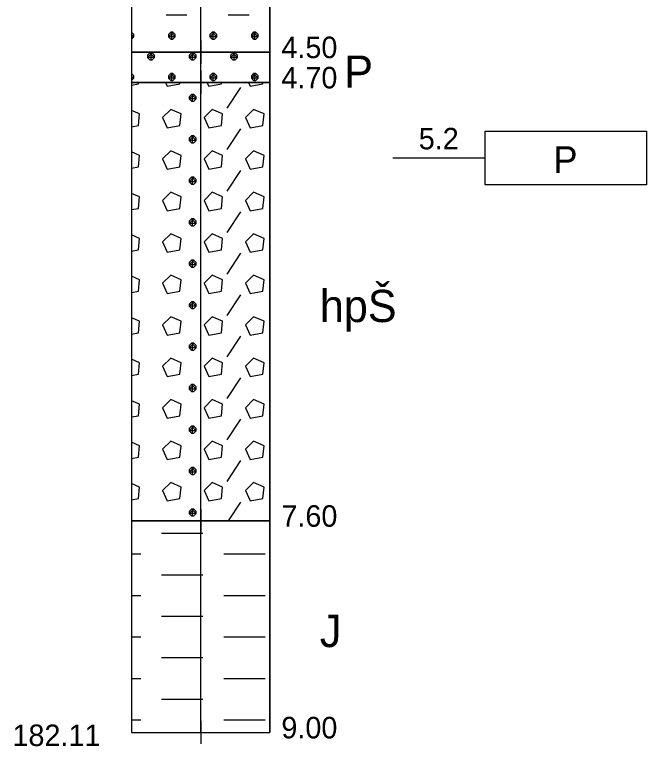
# Model space of a CAD drawing. Extents: x 3042 to 4120, y 576 to 2694.
# Drawn here: x 3706.2 to 3727.08, y 1007.43 to 1031.63 of the extents above; entities that cross this region are included whole.
import ezdxf

# ---------------------------------------------------------------- set-up
doc = ezdxf.new("R2010")
doc.units = 0
for name, color, linetype in [('17', 7, 'Continuous'), ('18', 7, 'Continuous'), ('51', 7, 'Continuous'), ('52', 7, 'Continuous'), ('53', 7, 'Continuous'), ('56', 7, 'Continuous'), ('62', 7, 'Continuous')]:
    doc.layers.add(name, color=color, linetype=linetype)

msp = doc.modelspace()

# ---------------------------------------------------------------- linework, layer by layer
at = {"layer": '18'}
for p, q in [((3712.347, 1007.89), (3712.347, 1052.89)), ((3712.347, 1008.271), (3712.347, 1007.509)), ((3711.966, 1007.89), (3712.728, 1007.89))]:
    msp.add_line(p, q, dxfattribs=at)
at = {"layer": '51'}
for p, q in [((3711.201, 1031.623), (3711.887, 1031.623)), ((3713.259, 1031.623), (3713.944, 1031.623)), ((3710.058, 1031.051), (3710.058, 1031.051)), ((3711.392, 1030.822), (3711.392, 1031.051)), ((3712.763, 1030.822), (3712.763, 1031.051)), ((3714.135, 1030.822), (3714.135, 1031.051)), ((3710.706, 1030.137), (3710.706, 1030.365)), ((3712.077, 1030.137), (3712.077, 1030.365)), ((3713.449, 1030.137), (3713.449, 1030.365)), ((3710.058, 1029.679), (3710.058, 1029.679)), ((3711.392, 1029.451), (3711.392, 1029.679)), ((3712.763, 1029.451), (3712.763, 1029.679)), ((3714.135, 1029.451), (3714.135, 1029.679)), ((3713.22, 1028.536), (3713.678, 1029.222)), ((3712.077, 1028.765), (3712.077, 1028.994)), ((3713.22, 1027.165), (3713.678, 1027.851)), ((3712.077, 1027.393), (3712.077, 1027.622)), ((3713.22, 1025.793), (3713.678, 1026.479)), ((3712.077, 1026.022), (3712.077, 1026.25)), ((3713.22, 1024.422), (3713.678, 1025.107)), ((3712.077, 1024.65), (3712.077, 1024.879)), ((3713.22, 1023.05), (3713.678, 1023.736)), ((3712.077, 1023.279), (3712.077, 1023.507)), ((3713.22, 1021.678), (3713.678, 1022.364)), ((3712.077, 1021.907), (3712.077, 1022.136)), ((3713.22, 1020.307), (3713.678, 1020.993)), ((3712.077, 1020.535), (3712.077, 1020.764)), ((3713.22, 1018.935), (3713.678, 1019.621)), ((3712.077, 1019.164), (3712.077, 1019.392)), ((3713.22, 1017.564), (3713.678, 1018.249)), ((3712.077, 1017.792), (3712.077, 1018.021)), ((3713.22, 1016.192), (3713.678, 1016.878)), ((3712.077, 1016.421), (3712.077, 1016.649)), ((3713.267, 1014.89), (3713.678, 1015.506)), ((3712.077, 1015.049), (3712.077, 1015.278)), ((3711.049, 1014.478), (3711.735, 1014.478)), ((3711.735, 1014.478), (3712.42, 1014.478)), ((3710.061, 1013.792), (3710.363, 1013.792)), ((3713.106, 1013.792), (3713.792, 1013.792)), ((3713.792, 1013.792), (3714.478, 1013.792)), ((3711.049, 1013.106), (3711.735, 1013.106)), ((3711.735, 1013.106), (3712.42, 1013.106)), ((3710.061, 1012.42), (3710.363, 1012.42)), ((3713.106, 1012.42), (3713.792, 1012.42)), ((3713.792, 1012.42), (3714.478, 1012.42)), ((3711.049, 1011.734), (3711.735, 1011.734)), ((3711.735, 1011.734), (3712.42, 1011.734)), ((3710.061, 1011.049), (3710.363, 1011.049)), ((3713.106, 1011.049), (3713.792, 1011.049)), ((3713.792, 1011.049), (3714.478, 1011.049)), ((3711.049, 1010.363), (3711.735, 1010.363)), ((3711.735, 1010.363), (3712.42, 1010.363)), ((3710.061, 1009.677), (3710.363, 1009.677)), ((3713.106, 1009.677), (3713.792, 1009.677)), ((3713.792, 1009.677), (3714.478, 1009.677)), ((3711.049, 1008.991), (3711.735, 1008.991)), ((3711.735, 1008.991), (3712.42, 1008.991)), ((3710.061, 1008.305), (3710.363, 1008.305)), ((3713.106, 1008.305), (3713.792, 1008.305)), ((3713.792, 1008.305), (3714.478, 1008.305))]:
    msp.add_line(p, q, dxfattribs=at)
for points in [[(3710.061, 1030.39), (3714.633, 1030.39), (3714.633, 1034.89), (3710.061, 1034.89)], [(3710.061, 1029.39), (3714.633, 1029.39), (3714.633, 1030.39), (3710.061, 1030.39)], [(3710.061, 1014.89), (3714.633, 1014.89), (3714.633, 1029.39), (3710.061, 1029.39)], [(3710.061, 1007.89), (3714.633, 1007.89), (3714.633, 1014.89), (3710.061, 1014.89)]]:
    msp.add_lwpolyline(points, close=True, dxfattribs=at)
for points in [[(3710.058, 1030.822), (3710.058, 1030.822), (3710.134, 1030.899), (3710.134, 1030.975), (3710.058, 1031.051), (3710.058, 1031.051)], [(3710.061, 1030.972), (3710.134, 1030.899), (3710.061, 1030.899)], [(3711.354, 1031.051), (3711.277, 1030.975), (3711.277, 1030.899), (3711.354, 1030.822), (3711.43, 1030.822), (3711.506, 1030.899), (3711.506, 1030.975), (3711.43, 1031.051), (3711.354, 1031.051), (3711.506, 1030.899), (3711.277, 1030.899), (3711.43, 1031.051)], [(3712.725, 1031.051), (3712.649, 1030.975), (3712.649, 1030.899), (3712.725, 1030.822), (3712.801, 1030.822), (3712.878, 1030.899), (3712.878, 1030.975), (3712.801, 1031.051), (3712.725, 1031.051), (3712.878, 1030.899), (3712.649, 1030.899), (3712.801, 1031.051)], [(3714.097, 1031.051), (3714.021, 1030.975), (3714.021, 1030.899), (3714.097, 1030.822), (3714.173, 1030.822), (3714.249, 1030.899), (3714.249, 1030.975), (3714.173, 1031.051), (3714.097, 1031.051), (3714.249, 1030.899), (3714.021, 1030.899), (3714.173, 1031.051)], [(3710.668, 1030.365), (3710.592, 1030.289), (3710.592, 1030.213), (3710.668, 1030.137), (3710.744, 1030.137), (3710.82, 1030.213), (3710.82, 1030.289), (3710.744, 1030.365), (3710.668, 1030.365), (3710.82, 1030.213), (3710.592, 1030.213), (3710.744, 1030.365)], [(3712.039, 1030.365), (3711.963, 1030.289), (3711.963, 1030.213), (3712.039, 1030.137), (3712.116, 1030.137), (3712.192, 1030.213), (3712.192, 1030.289), (3712.116, 1030.365), (3712.039, 1030.365), (3712.192, 1030.213), (3711.963, 1030.213), (3712.116, 1030.365)], [(3713.411, 1030.365), (3713.335, 1030.289), (3713.335, 1030.213), (3713.411, 1030.137), (3713.487, 1030.137), (3713.563, 1030.213), (3713.563, 1030.289), (3713.487, 1030.365), (3713.411, 1030.365), (3713.563, 1030.213), (3713.335, 1030.213), (3713.487, 1030.365)], [(3710.058, 1029.451), (3710.058, 1029.451), (3710.134, 1029.527), (3710.134, 1029.603), (3710.058, 1029.679), (3710.058, 1029.679)], [(3711.354, 1029.679), (3711.277, 1029.603), (3711.277, 1029.527), (3711.354, 1029.451), (3711.43, 1029.451), (3711.506, 1029.527), (3711.506, 1029.603), (3711.43, 1029.679), (3711.354, 1029.679), (3711.506, 1029.527), (3711.277, 1029.527), (3711.43, 1029.679)], [(3712.725, 1029.679), (3712.649, 1029.603), (3712.649, 1029.527), (3712.725, 1029.451), (3712.801, 1029.451), (3712.878, 1029.527), (3712.878, 1029.603), (3712.801, 1029.679), (3712.725, 1029.679), (3712.878, 1029.527), (3712.649, 1029.527), (3712.801, 1029.679)], [(3714.097, 1029.679), (3714.021, 1029.603), (3714.021, 1029.527), (3714.097, 1029.451), (3714.173, 1029.451), (3714.249, 1029.527), (3714.249, 1029.603), (3714.173, 1029.679), (3714.097, 1029.679), (3714.249, 1029.527), (3714.021, 1029.527), (3714.173, 1029.679)], [(3710.061, 1029.601), (3710.134, 1029.527), (3710.061, 1029.527)], [(3710.061, 1029.295), (3710.287, 1029.337), (3710.292, 1029.39)], [(3711.182, 1029.39), (3711.239, 1029.26), (3711.658, 1029.337), (3711.664, 1029.39)], [(3712.553, 1029.39), (3712.611, 1029.26), (3713.03, 1029.337), (3713.035, 1029.39)], [(3713.925, 1029.39), (3713.982, 1029.26), (3714.402, 1029.337), (3714.407, 1029.39)], [(3712.039, 1028.994), (3711.963, 1028.917), (3711.963, 1028.841), (3712.039, 1028.765), (3712.116, 1028.765), (3712.192, 1028.841), (3712.192, 1028.917), (3712.116, 1028.994), (3712.039, 1028.994), (3712.192, 1028.841), (3711.963, 1028.841), (3712.116, 1028.994)], [(3710.061, 1027.924), (3710.287, 1027.965), (3710.325, 1028.346), (3710.061, 1028.463)], [(3711.087, 1028.232), (3711.239, 1027.889), (3711.658, 1027.965), (3711.696, 1028.346), (3711.354, 1028.498), (3711.087, 1028.232)], [(3712.458, 1028.232), (3712.611, 1027.889), (3713.03, 1027.965), (3713.068, 1028.346), (3712.725, 1028.498), (3712.458, 1028.232)], [(3713.83, 1028.232), (3713.982, 1027.889), (3714.402, 1027.965), (3714.44, 1028.346), (3714.097, 1028.498), (3713.83, 1028.232)], [(3712.039, 1027.622), (3711.963, 1027.546), (3711.963, 1027.47), (3712.039, 1027.393), (3712.116, 1027.393), (3712.192, 1027.47), (3712.192, 1027.546), (3712.116, 1027.622), (3712.039, 1027.622), (3712.192, 1027.47), (3711.963, 1027.47), (3712.116, 1027.622)], [(3710.061, 1026.552), (3710.287, 1026.593), (3710.325, 1026.974), (3710.061, 1027.092)], [(3711.087, 1026.86), (3711.239, 1026.517), (3711.658, 1026.593), (3711.696, 1026.974), (3711.354, 1027.127), (3711.087, 1026.86)], [(3712.458, 1026.86), (3712.611, 1026.517), (3713.03, 1026.593), (3713.068, 1026.974), (3712.725, 1027.127), (3712.458, 1026.86)], [(3713.83, 1026.86), (3713.982, 1026.517), (3714.402, 1026.593), (3714.44, 1026.974), (3714.097, 1027.127), (3713.83, 1026.86)], [(3712.039, 1026.25), (3711.963, 1026.174), (3711.963, 1026.098), (3712.039, 1026.022), (3712.116, 1026.022), (3712.192, 1026.098), (3712.192, 1026.174), (3712.116, 1026.25), (3712.039, 1026.25), (3712.192, 1026.098), (3711.963, 1026.098), (3712.116, 1026.25)], [(3711.087, 1025.488), (3711.239, 1025.146), (3711.658, 1025.222), (3711.696, 1025.603), (3711.354, 1025.755), (3711.087, 1025.488)], [(3712.458, 1025.488), (3712.611, 1025.146), (3713.03, 1025.222), (3713.068, 1025.603), (3712.725, 1025.755), (3712.458, 1025.488)], [(3713.83, 1025.488), (3713.982, 1025.146), (3714.402, 1025.222), (3714.44, 1025.603), (3714.097, 1025.755), (3713.83, 1025.488)], [(3710.061, 1025.181), (3710.287, 1025.222), (3710.325, 1025.603), (3710.061, 1025.72)], [(3712.039, 1024.879), (3711.963, 1024.803), (3711.963, 1024.726), (3712.039, 1024.65), (3712.116, 1024.65), (3712.192, 1024.726), (3712.192, 1024.803), (3712.116, 1024.879), (3712.039, 1024.879), (3712.192, 1024.726), (3711.963, 1024.726), (3712.116, 1024.879)], [(3710.061, 1023.809), (3710.287, 1023.85), (3710.325, 1024.231), (3710.061, 1024.349)], [(3711.087, 1024.117), (3711.239, 1023.774), (3711.658, 1023.85), (3711.696, 1024.231), (3711.354, 1024.384), (3711.087, 1024.117)], [(3712.458, 1024.117), (3712.611, 1023.774), (3713.03, 1023.85), (3713.068, 1024.231), (3712.725, 1024.384), (3712.458, 1024.117)], [(3713.83, 1024.117), (3713.982, 1023.774), (3714.402, 1023.85), (3714.44, 1024.231), (3714.097, 1024.384), (3713.83, 1024.117)], [(3712.039, 1023.507), (3711.963, 1023.431), (3711.963, 1023.355), (3712.039, 1023.279), (3712.116, 1023.279), (3712.192, 1023.355), (3712.192, 1023.431), (3712.116, 1023.507), (3712.039, 1023.507), (3712.192, 1023.355), (3711.963, 1023.355), (3712.116, 1023.507)], [(3710.061, 1022.437), (3710.287, 1022.479), (3710.325, 1022.86), (3710.061, 1022.977)], [(3711.087, 1022.745), (3711.239, 1022.402), (3711.658, 1022.479), (3711.696, 1022.86), (3711.354, 1023.012), (3711.087, 1022.745)], [(3712.458, 1022.745), (3712.611, 1022.402), (3713.03, 1022.479), (3713.068, 1022.86), (3712.725, 1023.012), (3712.458, 1022.745)], [(3713.83, 1022.745), (3713.982, 1022.402), (3714.402, 1022.479), (3714.44, 1022.86), (3714.097, 1023.012), (3713.83, 1022.745)], [(3712.039, 1022.136), (3711.963, 1022.059), (3711.963, 1021.983), (3712.039, 1021.907), (3712.116, 1021.907), (3712.192, 1021.983), (3712.192, 1022.059), (3712.116, 1022.136), (3712.039, 1022.136), (3712.192, 1021.983), (3711.963, 1021.983), (3712.116, 1022.136)], [(3711.087, 1021.374), (3711.239, 1021.031), (3711.658, 1021.107), (3711.696, 1021.488), (3711.354, 1021.64), (3711.087, 1021.374)], [(3712.458, 1021.374), (3712.611, 1021.031), (3713.03, 1021.107), (3713.068, 1021.488), (3712.725, 1021.64), (3712.458, 1021.374)], [(3713.83, 1021.374), (3713.982, 1021.031), (3714.402, 1021.107), (3714.44, 1021.488), (3714.097, 1021.64), (3713.83, 1021.374)], [(3710.061, 1021.066), (3710.287, 1021.107), (3710.325, 1021.488), (3710.061, 1021.605)], [(3712.039, 1020.764), (3711.963, 1020.688), (3711.963, 1020.612), (3712.039, 1020.535), (3712.116, 1020.535), (3712.192, 1020.612), (3712.192, 1020.688), (3712.116, 1020.764), (3712.039, 1020.764), (3712.192, 1020.612), (3711.963, 1020.612), (3712.116, 1020.764)], [(3710.061, 1019.694), (3710.287, 1019.735), (3710.325, 1020.116), (3710.061, 1020.234)], [(3711.087, 1020.002), (3711.239, 1019.659), (3711.658, 1019.735), (3711.696, 1020.116), (3711.354, 1020.269), (3711.087, 1020.002)], [(3712.458, 1020.002), (3712.611, 1019.659), (3713.03, 1019.735), (3713.068, 1020.116), (3712.725, 1020.269), (3712.458, 1020.002)], [(3713.83, 1020.002), (3713.982, 1019.659), (3714.402, 1019.735), (3714.44, 1020.116), (3714.097, 1020.269), (3713.83, 1020.002)], [(3712.039, 1019.392), (3711.963, 1019.316), (3711.963, 1019.24), (3712.039, 1019.164), (3712.116, 1019.164), (3712.192, 1019.24), (3712.192, 1019.316), (3712.116, 1019.392), (3712.039, 1019.392), (3712.192, 1019.24), (3711.963, 1019.24), (3712.116, 1019.392)], [(3710.061, 1018.323), (3710.287, 1018.364), (3710.325, 1018.745), (3710.061, 1018.862)], [(3711.087, 1018.63), (3711.239, 1018.288), (3711.658, 1018.364), (3711.696, 1018.745), (3711.354, 1018.897), (3711.087, 1018.63)], [(3712.458, 1018.63), (3712.611, 1018.288), (3713.03, 1018.364), (3713.068, 1018.745), (3712.725, 1018.897), (3712.458, 1018.63)], [(3713.83, 1018.63), (3713.982, 1018.288), (3714.402, 1018.364), (3714.44, 1018.745), (3714.097, 1018.897), (3713.83, 1018.63)], [(3712.039, 1018.021), (3711.963, 1017.945), (3711.963, 1017.868), (3712.039, 1017.792), (3712.116, 1017.792), (3712.192, 1017.868), (3712.192, 1017.945), (3712.116, 1018.021), (3712.039, 1018.021), (3712.192, 1017.868), (3711.963, 1017.868), (3712.116, 1018.021)], [(3711.087, 1017.259), (3711.239, 1016.916), (3711.658, 1016.992), (3711.696, 1017.373), (3711.354, 1017.526), (3711.087, 1017.259)], [(3712.458, 1017.259), (3712.611, 1016.916), (3713.03, 1016.992), (3713.068, 1017.373), (3712.725, 1017.526), (3712.458, 1017.259)], [(3713.83, 1017.259), (3713.982, 1016.916), (3714.402, 1016.992), (3714.44, 1017.373), (3714.097, 1017.526), (3713.83, 1017.259)], [(3710.061, 1016.951), (3710.287, 1016.992), (3710.325, 1017.373), (3710.061, 1017.491)], [(3712.039, 1016.649), (3711.963, 1016.573), (3711.963, 1016.497), (3712.039, 1016.421), (3712.116, 1016.421), (3712.192, 1016.497), (3712.192, 1016.573), (3712.116, 1016.649), (3712.039, 1016.649), (3712.192, 1016.497), (3711.963, 1016.497), (3712.116, 1016.649)], [(3710.061, 1015.579), (3710.287, 1015.621), (3710.325, 1016.002), (3710.061, 1016.119)], [(3711.087, 1015.887), (3711.239, 1015.544), (3711.658, 1015.621), (3711.696, 1016.002), (3711.354, 1016.154), (3711.087, 1015.887)], [(3712.458, 1015.887), (3712.611, 1015.544), (3713.03, 1015.621), (3713.068, 1016.002), (3712.725, 1016.154), (3712.458, 1015.887)], [(3713.83, 1015.887), (3713.982, 1015.544), (3714.402, 1015.621), (3714.44, 1016.002), (3714.097, 1016.154), (3713.83, 1015.887)], [(3712.039, 1015.278), (3711.963, 1015.201), (3711.963, 1015.125), (3712.039, 1015.049), (3712.116, 1015.049), (3712.192, 1015.125), (3712.192, 1015.201), (3712.116, 1015.278), (3712.039, 1015.278), (3712.192, 1015.125), (3711.963, 1015.125), (3712.116, 1015.278)]]:
    msp.add_lwpolyline(points, dxfattribs=at)
at = {"layer": '53'}
for p, q in [((3710.061, 1052.89), (3710.061, 1007.89)), ((3714.633, 1052.89), (3714.633, 1007.89)), ((3710.061, 1030.39), (3714.633, 1030.39)), ((3710.061, 1029.39), (3714.633, 1029.39)), ((3710.061, 1014.89), (3714.633, 1014.89)), ((3710.061, 1007.89), (3714.633, 1007.89))]:
    msp.add_line(p, q, dxfattribs=at)
at = {"layer": '56'}
for p, q in [((3712.347, 1030.771), (3712.347, 1030.009)), ((3711.966, 1030.39), (3712.728, 1030.39)), ((3712.347, 1029.771), (3712.347, 1029.009)), ((3711.966, 1029.39), (3712.728, 1029.39)), ((3712.347, 1015.271), (3712.347, 1014.509)), ((3711.966, 1014.89), (3712.728, 1014.89)), ((3712.347, 1008.271), (3712.347, 1007.509)), ((3711.966, 1007.89), (3712.728, 1007.89))]:
    msp.add_line(p, q, dxfattribs=at)
at = {"layer": '62'}
msp.add_line((3718.697, 1026.89), (3721.745, 1026.89), dxfattribs=at)
msp.add_lwpolyline([(3727.079, 1026.001), (3721.745, 1026.001), (3721.745, 1027.779), (3727.079, 1027.779), (3727.079, 1026.001)], dxfattribs=at)

# ---------------------------------------------------------------- texts
at = {"layer": '17'}
msp.add_text('182.11', height=0.7112, dxfattribs=at).set_placement((3706.124, 1007.438))
at = {"layer": '52'}
for s, height, p in [('4.50', 0.7112, (3715.014, 1030.192)), ('P', 1.067, (3717.091, 1029.212)), ('4.70', 0.7112, (3715.014, 1029.192)), ('hpŠ', 1.0668, (3716.284, 1021.462)), ('7.60', 0.7112, (3715.014, 1014.692)), ('J', 1.067, (3716.284, 1010.712)), ('9.00', 0.7112, (3715.014, 1007.692))]:
    msp.add_text(s, height=height, dxfattribs=at).set_placement(p)
at = {"layer": '62'}
for s, height, p in [('5.2', 0.7112, (3719.554, 1027.175)), ('P', 0.889, (3724.01, 1026.388))]:
    msp.add_text(s, height=height, dxfattribs=at).set_placement(p)

doc.saveas('drawing.dxf')
